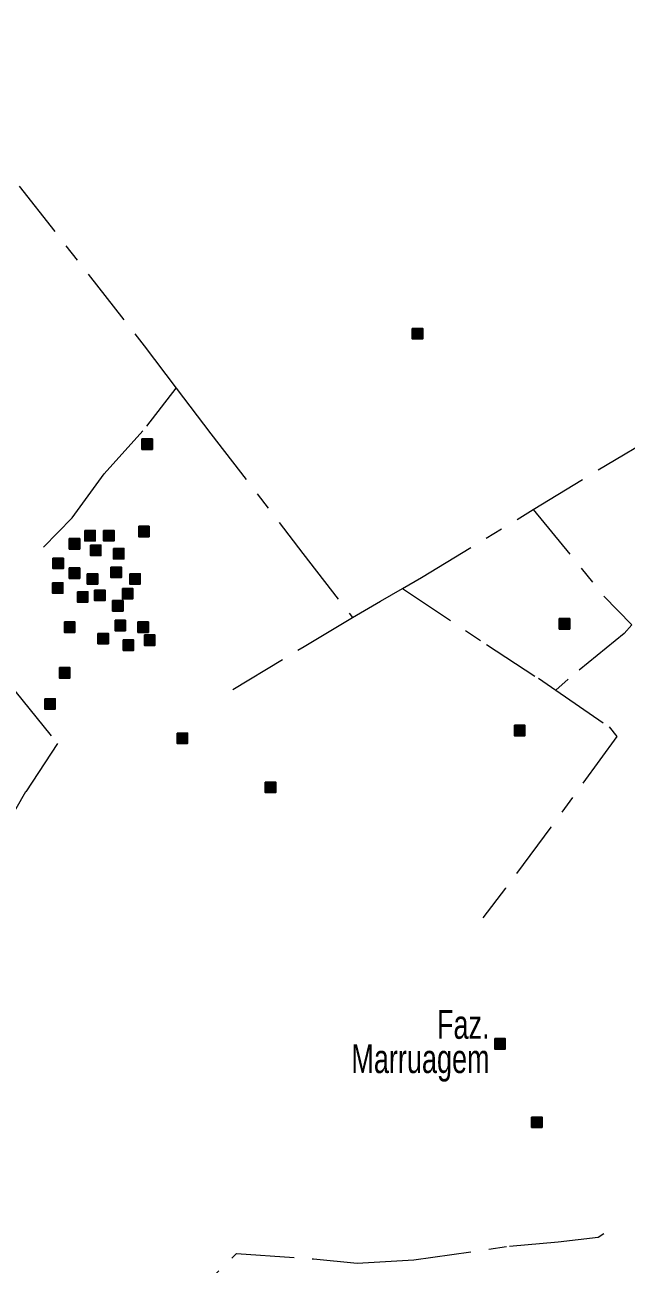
# Model space of a CAD drawing. Extents: x 445.4 to 500, y 8728.7 to 8784.
# Drawn here: x 468.75 to 472.09, y 8739.94 to 8746.8 of the extents above; entities that cross this region are included whole.
import ezdxf
from ezdxf.enums import TextEntityAlignment as Align

# ---------------------------------------------------------------- set-up
doc = ezdxf.new("R2010")
doc.units = 0
doc.header["$LTSCALE"] = 0.064
doc.linetypes.add('DOT_DASHED', pattern=[7.7, 5, -1.2, 0.3, -1.2])
doc.layers.add('2', color=7, linetype='Continuous', lineweight=25)
doc.layers.add('22', color=7, linetype='DOT_DASHED', lineweight=13)
doc.layers.add('61', color=7, linetype='Continuous')

msp = doc.modelspace()

# ---------------------------------------------------------------- hatches: boundary and pattern name
at = {"layer": '2'}
for points in [[(470.9015, 8745.1218), (470.9595, 8745.1218), (470.9595, 8745.0638), (470.9015, 8745.0638)], [(469.4038, 8744.5097), (469.4618, 8744.5097), (469.4618, 8744.4517), (469.4038, 8744.4517)], [(469.0871, 8744.0026), (469.1451, 8744.0026), (469.1451, 8743.9446), (469.0871, 8743.9446)], [(469.1911, 8744.0026), (469.2491, 8744.0026), (469.2491, 8743.9446), (469.1911, 8743.9446)], [(469.3857, 8744.0253), (469.4437, 8744.0253), (469.4437, 8743.9673), (469.3857, 8743.9673)], [(469.0011, 8743.9573), (469.0591, 8743.9573), (469.0591, 8743.8993), (469.0011, 8743.8993)], [(469.1187, 8743.9211), (469.1767, 8743.9211), (469.1767, 8743.8631), (469.1187, 8743.8631)], [(469.2454, 8743.903), (469.3034, 8743.903), (469.3034, 8743.845), (469.2454, 8743.845)], [(468.9106, 8743.8487), (468.9686, 8743.8487), (468.9686, 8743.7907), (468.9106, 8743.7907)], [(469.0011, 8743.7944), (469.0591, 8743.7944), (469.0591, 8743.7364), (469.0011, 8743.7364)], [(469.1006, 8743.7627), (469.1586, 8743.7627), (469.1586, 8743.7047), (469.1006, 8743.7047)], [(469.2319, 8743.7989), (469.2899, 8743.7989), (469.2899, 8743.7409), (469.2319, 8743.7409)], [(469.3359, 8743.7627), (469.3939, 8743.7627), (469.3939, 8743.7047), (469.3359, 8743.7047)], [(468.9082, 8743.7126), (468.9662, 8743.7126), (468.9662, 8743.6546), (468.9082, 8743.6546)], [(469.0463, 8743.6631), (469.1043, 8743.6631), (469.1043, 8743.6051), (469.0463, 8743.6051)], [(469.1414, 8743.6721), (469.1994, 8743.6721), (469.1994, 8743.6141), (469.1414, 8743.6141)], [(469.2952, 8743.6812), (469.3532, 8743.6812), (469.3532, 8743.6232), (469.2952, 8743.6232)], [(469.2409, 8743.6133), (469.2989, 8743.6133), (469.2989, 8743.5553), (469.2409, 8743.5553)], [(468.9739, 8743.4955), (469.0319, 8743.4955), (469.0319, 8743.4375), (468.9739, 8743.4375)], [(469.2545, 8743.5046), (469.3125, 8743.5046), (469.3125, 8743.4466), (469.2545, 8743.4466)], [(469.3812, 8743.4955), (469.4392, 8743.4955), (469.4392, 8743.4375), (469.3812, 8743.4375)], [(471.7161, 8743.5137), (471.7741, 8743.5137), (471.7741, 8743.4557), (471.7161, 8743.4557)], [(469.1595, 8743.4322), (469.2175, 8743.4322), (469.2175, 8743.3742), (469.1595, 8743.3742)], [(469.4174, 8743.4231), (469.4754, 8743.4231), (469.4754, 8743.3651), (469.4174, 8743.3651)], [(469.2997, 8743.3959), (469.3577, 8743.3959), (469.3577, 8743.3379), (469.2997, 8743.3379)], [(468.9468, 8743.242), (469.0048, 8743.242), (469.0048, 8743.184), (468.9468, 8743.184)], [(468.8653, 8743.07), (468.9233, 8743.07), (468.9233, 8743.012), (468.8653, 8743.012)], [(469.5984, 8742.8798), (469.6564, 8742.8798), (469.6564, 8742.8218), (469.5984, 8742.8218)], [(471.4671, 8742.9225), (471.5251, 8742.9225), (471.5251, 8742.8645), (471.4671, 8742.8645)], [(470.0871, 8742.6082), (470.1451, 8742.6082), (470.1451, 8742.5502), (470.0871, 8742.5502)], [(471.3586, 8741.1865), (471.4166, 8741.1865), (471.4166, 8741.1285), (471.3586, 8741.1285)], [(471.5622, 8740.7519), (471.6202, 8740.7519), (471.6202, 8740.6939), (471.5622, 8740.6939)]]:
    msp.add_hatch(color=256, dxfattribs=at).paths.add_polyline_path(points)

# ---------------------------------------------------------------- linework, layer by layer
for points in [[(470.9015, 8745.1218), (470.9595, 8745.1218), (470.9595, 8745.0638), (470.9015, 8745.0638)], [(469.4038, 8744.5097), (469.4618, 8744.5097), (469.4618, 8744.4517), (469.4038, 8744.4517)], [(469.0871, 8744.0026), (469.1451, 8744.0026), (469.1451, 8743.9446), (469.0871, 8743.9446)], [(469.1911, 8744.0026), (469.2491, 8744.0026), (469.2491, 8743.9446), (469.1911, 8743.9446)], [(469.3857, 8744.0253), (469.4437, 8744.0253), (469.4437, 8743.9673), (469.3857, 8743.9673)], [(469.0011, 8743.9573), (469.0591, 8743.9573), (469.0591, 8743.8993), (469.0011, 8743.8993)], [(469.1187, 8743.9211), (469.1767, 8743.9211), (469.1767, 8743.8631), (469.1187, 8743.8631)], [(469.2454, 8743.903), (469.3034, 8743.903), (469.3034, 8743.845), (469.2454, 8743.845)], [(468.9106, 8743.8487), (468.9686, 8743.8487), (468.9686, 8743.7907), (468.9106, 8743.7907)], [(469.0011, 8743.7944), (469.0591, 8743.7944), (469.0591, 8743.7364), (469.0011, 8743.7364)], [(469.1006, 8743.7627), (469.1586, 8743.7627), (469.1586, 8743.7047), (469.1006, 8743.7047)], [(469.2319, 8743.7989), (469.2899, 8743.7989), (469.2899, 8743.7409), (469.2319, 8743.7409)], [(469.3359, 8743.7627), (469.3939, 8743.7627), (469.3939, 8743.7047), (469.3359, 8743.7047)], [(468.9082, 8743.7126), (468.9662, 8743.7126), (468.9662, 8743.6546), (468.9082, 8743.6546)], [(469.0463, 8743.6631), (469.1043, 8743.6631), (469.1043, 8743.6051), (469.0463, 8743.6051)], [(469.1414, 8743.6721), (469.1994, 8743.6721), (469.1994, 8743.6141), (469.1414, 8743.6141)], [(469.2952, 8743.6812), (469.3532, 8743.6812), (469.3532, 8743.6232), (469.2952, 8743.6232)], [(469.2409, 8743.6133), (469.2989, 8743.6133), (469.2989, 8743.5553), (469.2409, 8743.5553)], [(468.9739, 8743.4955), (469.0319, 8743.4955), (469.0319, 8743.4375), (468.9739, 8743.4375)], [(469.2545, 8743.5046), (469.3125, 8743.5046), (469.3125, 8743.4466), (469.2545, 8743.4466)], [(469.3812, 8743.4955), (469.4392, 8743.4955), (469.4392, 8743.4375), (469.3812, 8743.4375)], [(471.7161, 8743.5137), (471.7741, 8743.5137), (471.7741, 8743.4557), (471.7161, 8743.4557)], [(469.1595, 8743.4322), (469.2175, 8743.4322), (469.2175, 8743.3742), (469.1595, 8743.3742)], [(469.4174, 8743.4231), (469.4754, 8743.4231), (469.4754, 8743.3651), (469.4174, 8743.3651)], [(469.2997, 8743.3959), (469.3577, 8743.3959), (469.3577, 8743.3379), (469.2997, 8743.3379)], [(468.9468, 8743.242), (469.0048, 8743.242), (469.0048, 8743.184), (468.9468, 8743.184)], [(468.8653, 8743.07), (468.9233, 8743.07), (468.9233, 8743.012), (468.8653, 8743.012)], [(469.5984, 8742.8798), (469.6564, 8742.8798), (469.6564, 8742.8218), (469.5984, 8742.8218)], [(471.4671, 8742.9225), (471.5251, 8742.9225), (471.5251, 8742.8645), (471.4671, 8742.8645)], [(470.0871, 8742.6082), (470.1451, 8742.6082), (470.1451, 8742.5502), (470.0871, 8742.5502)], [(471.3586, 8741.1865), (471.4166, 8741.1865), (471.4166, 8741.1285), (471.3586, 8741.1285)], [(471.5622, 8740.7519), (471.6202, 8740.7519), (471.6202, 8740.6939), (471.5622, 8740.6939)]]:
    msp.add_lwpolyline(points, close=True, dxfattribs=at)
at = {"layer": '22'}
for points in [[(468.0542, 8746.8045), (468.4997, 8746.2198), (468.7237, 8745.9106), (469.4163, 8745.0253), (469.5937, 8744.7911)], [(468.859, 8743.9101), (469.0166, 8744.0728), (469.1945, 8744.3162), (469.4317, 8744.5794), (469.5937, 8744.7911)], [(469.5937, 8744.7911), (469.7852, 8744.5383), (470.2948, 8743.8754), (470.5707, 8743.5194), (470.5715, 8743.5184)], [(471.5719, 8744.1188), (471.9722, 8744.3629), (472.4809, 8744.6653), (472.5709, 8744.7288)], [(470.8481, 8743.6812), (470.9526, 8743.741), (471.5719, 8744.1188)], [(471.5719, 8744.1188), (471.9633, 8743.6383), (472.1181, 8743.4787), (472.0746, 8743.4308), (471.7655, 8743.1787), (471.6959, 8743.1178)], [(470.5707, 8743.5194), (470.7255, 8743.611), (470.8481, 8743.6812)], [(470.8481, 8743.6812), (471.3129, 8743.37), (471.6001, 8743.1831), (471.6959, 8743.1178)], [(469.908, 8743.1211), (470.3016, 8743.36), (470.5707, 8743.5194)], [(468.6989, 8743.1132), (468.9354, 8742.8222), (468.7584, 8742.553), (468.611, 8742.2963), (468.4789, 8742.0685), (468.4048, 8742.0669), (468.0171, 8742.3384), (467.9328, 8742.3847), (467.7047, 8742.5385)], [(471.6959, 8743.1178), (471.9919, 8742.9135), (472.0354, 8742.8614), (471.6696, 8742.3584), (471.4172, 8742.0194), (471.2921, 8741.8555)], [(468.9955, 8739.0878), (469.6043, 8739.6727), (469.9279, 8739.9964), (470.3543, 8739.9657), (470.5967, 8739.9412), (470.9096, 8739.9596), (471.4404, 8740.0362), (471.7097, 8740.0611), (471.9305, 8740.0856), (471.963, 8740.1073)]]:
    msp.add_lwpolyline(points, dxfattribs=at)

# ---------------------------------------------------------------- texts
at = {"layer": '61', "width": 0.7}
for s, p in [('          Faz.', (471.3297, 8741.1854)), ('Marruagem', (471.3297, 8740.9954))]:
    msp.add_text(s, height=0.16, dxfattribs=at).set_placement(p, align=Align.RIGHT)

doc.saveas('drawing.dxf')
